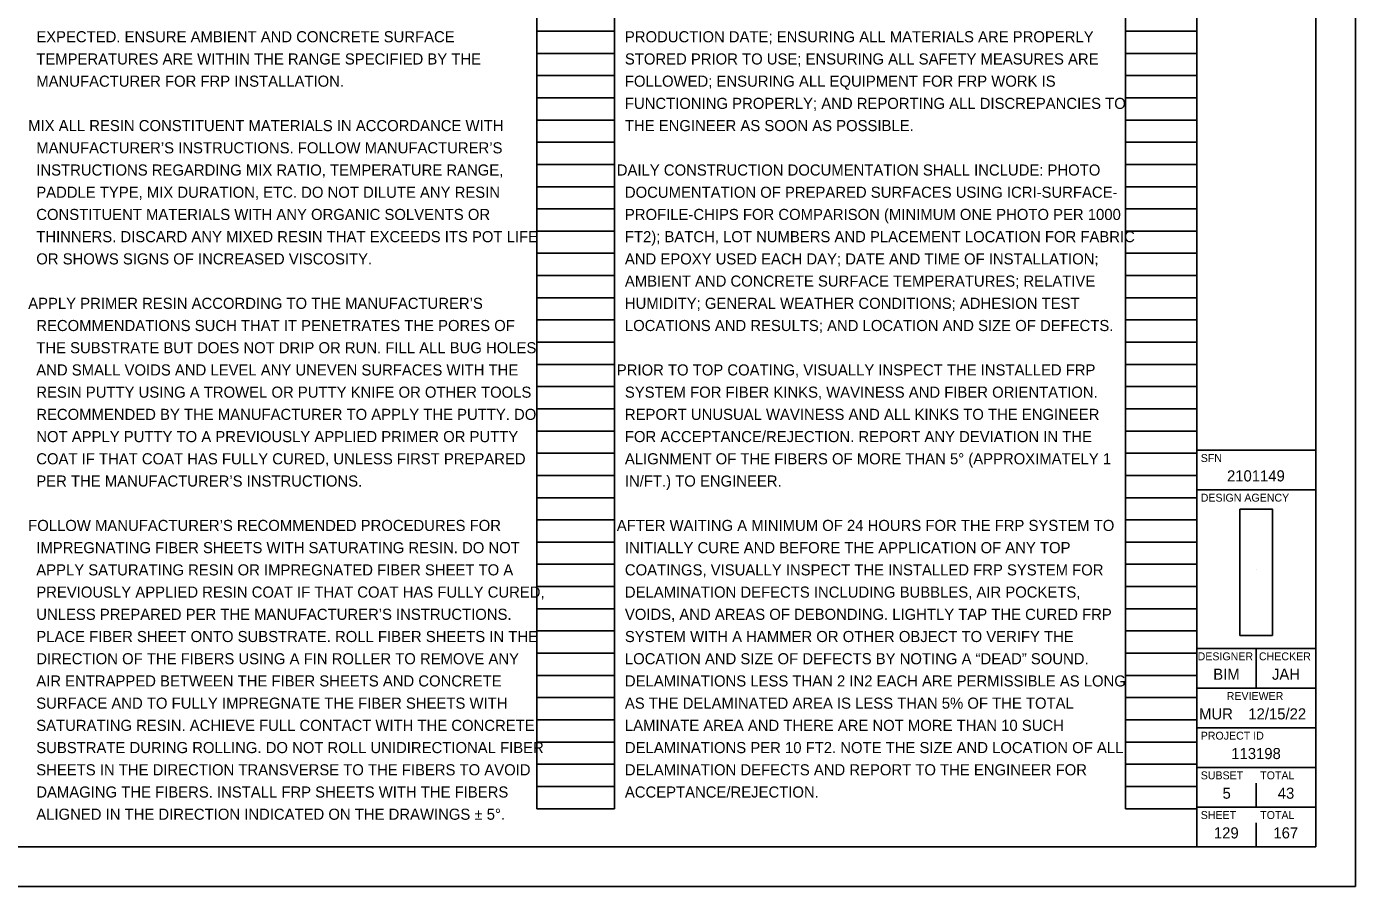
# Model space of a CAD drawing. Extents: x 0 to 90.2, y -3.7 to 22.
# Drawn here: x 17.25 to 34, y 0 to 10.84 of the extents above; entities that cross this region are included whole.
import ezdxf

# ---------------------------------------------------------------- set-up
doc = ezdxf.new("R2010")
doc.units = 0
for name, color, linetype in [('Default', 7, 'Continuous'), ('SH_Border', 7, 'Continuous'), ('SH_Cut_Line', 7, 'Continuous'), ('SH_Data', 7, 'Continuous'), ('SH_Text', 7, 'Continuous')]:
    doc.layers.add(name, color=color, linetype=linetype)

msp = doc.modelspace()

# ---------------------------------------------------------------- linework, layer by layer
at = {"layer": 'SH_Border'}
for p, q in [((32, 0.5), (32, 21.5)), ((32, 5.5), (33.5, 5.5)), ((32, 5), (33.5, 5)), ((32, 3), (33.5, 3)), ((32.75, 3), (32.75, 2.5)), ((32, 2.5), (33.5, 2.5)), ((32, 2), (33.5, 2)), ((32, 1.5), (33.5, 1.5)), ((32, 1), (33.5, 1))]:
    msp.add_line(p, q, dxfattribs=at)
msp.add_lwpolyline([(1.5, 21.5), (33.5, 21.5), (33.5, 0.5), (1.5, 0.5)], close=True, dxfattribs=at)
at = {"layer": 'SH_Cut_Line'}
msp.add_lwpolyline([(0, 0), (34, 0), (34, 22), (0, 22)], close=True, dxfattribs=at)
at = {"layer": 'SH_Data'}
for p, q in [((23.68, 0.98), (23.68, 21.14)), ((24.66, 0.98), (24.66, 21.14)), ((31.1, 0.98), (31.1, 21.14)), ((32, 0.98), (32, 21.14)), ((23.68, 10.78), (24.66, 10.78)), ((31.1, 10.78), (32, 10.78)), ((23.68, 10.5), (24.66, 10.5)), ((31.1, 10.5), (32, 10.5)), ((23.68, 10.22), (24.66, 10.22)), ((31.1, 10.22), (32, 10.22)), ((23.68, 9.94), (24.66, 9.94)), ((31.1, 9.94), (32, 9.94)), ((23.68, 9.66), (24.66, 9.66)), ((31.1, 9.66), (32, 9.66)), ((23.68, 9.38), (24.66, 9.38)), ((31.1, 9.38), (32, 9.38)), ((23.68, 9.1), (24.66, 9.1)), ((31.1, 9.1), (32, 9.1)), ((23.68, 8.82), (24.66, 8.82)), ((31.1, 8.82), (32, 8.82)), ((23.68, 8.54), (24.66, 8.54)), ((31.1, 8.54), (32, 8.54)), ((23.68, 8.26), (24.66, 8.26)), ((31.1, 8.26), (32, 8.26)), ((23.68, 7.98), (24.66, 7.98)), ((31.1, 7.98), (32, 7.98)), ((23.68, 7.7), (24.66, 7.7)), ((31.1, 7.7), (32, 7.7)), ((23.68, 7.42), (24.66, 7.42)), ((31.1, 7.42), (32, 7.42)), ((23.68, 7.14), (24.66, 7.14)), ((31.1, 7.14), (32, 7.14)), ((23.68, 6.86), (24.66, 6.86)), ((31.1, 6.86), (32, 6.86)), ((23.68, 6.58), (24.66, 6.58)), ((31.1, 6.58), (32, 6.58)), ((23.68, 6.3), (24.66, 6.3)), ((31.1, 6.3), (32, 6.3)), ((23.68, 6.02), (24.66, 6.02)), ((31.1, 6.02), (32, 6.02)), ((23.68, 5.74), (24.66, 5.74)), ((31.1, 5.74), (32, 5.74)), ((23.68, 5.46), (24.66, 5.46)), ((31.1, 5.46), (32, 5.46)), ((23.68, 5.18), (24.66, 5.18)), ((31.1, 5.18), (32, 5.18)), ((23.68, 4.9), (24.66, 4.9)), ((31.1, 4.9), (32, 4.9)), ((23.68, 4.62), (24.66, 4.62)), ((31.1, 4.62), (32, 4.62)), ((23.68, 4.34), (24.66, 4.34)), ((31.1, 4.34), (32, 4.34)), ((23.68, 4.06), (24.66, 4.06)), ((31.1, 4.06), (32, 4.06)), ((32.75, 4), (32.75, 4)), ((23.68, 3.78), (24.66, 3.78)), ((31.1, 3.78), (32, 3.78)), ((23.68, 3.5), (24.66, 3.5)), ((31.1, 3.5), (32, 3.5)), ((23.68, 3.22), (24.66, 3.22)), ((31.1, 3.22), (32, 3.22)), ((23.68, 2.94), (24.66, 2.94)), ((31.1, 2.94), (32, 2.94)), ((23.68, 2.66), (24.66, 2.66)), ((31.1, 2.66), (32, 2.66)), ((23.68, 2.38), (24.66, 2.38)), ((31.1, 2.38), (32, 2.38)), ((23.68, 2.1), (24.66, 2.1)), ((31.1, 2.1), (32, 2.1)), ((23.68, 1.82), (24.66, 1.82)), ((31.1, 1.82), (32, 1.82)), ((23.68, 1.54), (24.66, 1.54)), ((31.1, 1.54), (32, 1.54)), ((23.68, 1.26), (24.66, 1.26)), ((31.1, 1.26), (32, 1.26)), ((32.75, 1), (32.75, 1.3)), ((23.68, 0.98), (24.66, 0.98)), ((31.1, 0.98), (32, 0.98)), ((32.375, 0.675), (32.375, 0.675)), ((32.75, 0.5), (32.75, 0.8))]:
    msp.add_line(p, q, dxfattribs=at)
at = {"layer": 'SH_Text'}
msp.add_lwpolyline([(32.956, 3.164), (32.956, 4.754), (32.544, 4.754), (32.544, 3.164)], close=True, dxfattribs=at)

# ---------------------------------------------------------------- texts
at = {"layer": 'Default'}
for s, p in [('EXPECTED. ENSURE AMBIENT AND CONCRETE SURFACE ', (17.371, 10.64)), ('PRODUCTION DATE; ENSURING ALL MATERIALS ARE PROPERLY ', (24.791, 10.64)), ('TEMPERATURES ARE WITHIN THE RANGE SPECIFIED BY THE ', (17.371, 10.36)), ('STORED PRIOR TO USE; ENSURING ALL SAFETY MEASURES ARE ', (24.791, 10.36)), ('MANUFACTURER FOR FRP INSTALLATION.', (17.371, 10.08)), ('FOLLOWED; ENSURING ALL EQUIPMENT FOR FRP WORK IS ', (24.791, 10.08)), ('FUNCTIONING PROPERLY; AND REPORTING ALL DISCREPANCIES TO ', (24.791, 9.8)), ('MIX ALL RESIN CONSTITUENT MATERIALS IN ACCORDANCE WITH ', (17.269, 9.52)), ('THE ENGINEER AS SOON AS POSSIBLE.', (24.791, 9.52)), ('MANUFACTURER’S INSTRUCTIONS. FOLLOW MANUFACTURER’S ', (17.371, 9.24)), ('INSTRUCTIONS REGARDING MIX RATIO, TEMPERATURE RANGE, ', (17.371, 8.96)), ('DAILY CONSTRUCTION DOCUMENTATION SHALL INCLUDE: PHOTO ', (24.689, 8.96)), ('PADDLE TYPE, MIX DURATION, ETC. DO NOT DILUTE ANY RESIN ', (17.371, 8.68)), ('DOCUMENTATION OF PREPARED SURFACES USING ICRI-SURFACE-', (24.791, 8.68)), ('PROFILE-CHIPS FOR COMPARISON (MINIMUM ONE PHOTO PER 1000 ', (24.791, 8.4)), ('CONSTITUENT MATERIALS WITH ANY ORGANIC SOLVENTS OR ', (17.371, 8.4)), ('THINNERS. DISCARD ANY MIXED RESIN THAT EXCEEDS ITS POT LIFE ', (17.371, 8.12)), ('FT2); BATCH, LOT NUMBERS AND PLACEMENT LOCATION FOR FABRIC ', (24.791, 8.12)), ('OR SHOWS SIGNS OF INCREASED VISCOSITY.', (17.371, 7.84)), ('AND EPOXY USED EACH DAY; DATE AND TIME OF INSTALLATION; ', (24.791, 7.84)), ('AMBIENT AND CONCRETE SURFACE TEMPERATURES; RELATIVE ', (24.791, 7.56)), ('APPLY PRIMER RESIN ACCORDING TO THE MANUFACTURER’S ', (17.269, 7.28)), ('HUMIDITY; GENERAL WEATHER CONDITIONS; ADHESION TEST ', (24.791, 7.28)), ('RECOMMENDATIONS SUCH THAT IT PENETRATES THE PORES OF ', (17.371, 7)), ('LOCATIONS AND RESULTS; AND LOCATION AND SIZE OF DEFECTS.', (24.791, 7)), ('THE SUBSTRATE BUT DOES NOT DRIP OR RUN. FILL ALL BUG HOLES ', (17.371, 6.72)), ('AND SMALL VOIDS AND LEVEL ANY UNEVEN SURFACES WITH THE ', (17.371, 6.44)), ('PRIOR TO TOP COATING, VISUALLY INSPECT THE INSTALLED FRP ', (24.689, 6.44)), ('RESIN PUTTY USING A TROWEL OR PUTTY KNIFE OR OTHER TOOLS ', (17.371, 6.16)), ('SYSTEM FOR FIBER KINKS, WAVINESS AND FIBER ORIENTATION. ', (24.791, 6.16)), ('RECOMMENDED BY THE MANUFACTURER TO APPLY THE PUTTY. DO ', (17.371, 5.88)), ('REPORT UNUSUAL WAVINESS AND ALL KINKS TO THE ENGINEER ', (24.791, 5.88)), ('NOT APPLY PUTTY TO A PREVIOUSLY APPLIED PRIMER OR PUTTY ', (17.371, 5.6)), ('FOR ACCEPTANCE/REJECTION. REPORT ANY DEVIATION IN THE ', (24.791, 5.6)), ('COAT IF THAT COAT HAS FULLY CURED, UNLESS FIRST PREPARED ', (17.371, 5.32)), ('ALIGNMENT OF THE FIBERS OF MORE THAN 5° (APPROXIMATELY 1 ', (24.791, 5.32)), ('PER THE MANUFACTURER’S INSTRUCTIONS.', (17.371, 5.04)), ('IN/FT.) TO ENGINEER.', (24.791, 5.04)), ('FOLLOW MANUFACTURER’S RECOMMENDED PROCEDURES FOR ', (17.269, 4.48)), ('AFTER WAITING A MINIMUM OF 24 HOURS FOR THE FRP SYSTEM TO ', (24.689, 4.48)), ('IMPREGNATING FIBER SHEETS WITH SATURATING RESIN. DO NOT ', (17.371, 4.2)), ('INITIALLY CURE AND BEFORE THE APPLICATION OF ANY TOP ', (24.791, 4.2)), ('APPLY SATURATING RESIN OR IMPREGNATED FIBER SHEET TO A ', (17.371, 3.92)), ('COATINGS, VISUALLY INSPECT THE INSTALLED FRP SYSTEM FOR ', (24.791, 3.92)), ('PREVIOUSLY APPLIED RESIN COAT IF THAT COAT HAS FULLY CURED, ', (17.371, 3.64)), ('DELAMINATION DEFECTS INCLUDING BUBBLES, AIR POCKETS, ', (24.791, 3.64)), ('UNLESS PREPARED PER THE MANUFACTURER’S INSTRUCTIONS. ', (17.371, 3.36)), ('VOIDS, AND AREAS OF DEBONDING. LIGHTLY TAP THE CURED FRP ', (24.791, 3.36)), ('PLACE FIBER SHEET ONTO SUBSTRATE. ROLL FIBER SHEETS IN THE ', (17.371, 3.08)), ('SYSTEM WITH A HAMMER OR OTHER OBJECT TO VERIFY THE ', (24.791, 3.08)), ('DIRECTION OF THE FIBERS USING A FIN ROLLER TO REMOVE ANY ', (17.371, 2.8)), ('LOCATION AND SIZE OF DEFECTS BY NOTING A “DEAD” SOUND. ', (24.791, 2.8)), ('AIR ENTRAPPED BETWEEN THE FIBER SHEETS AND CONCRETE ', (17.371, 2.52)), ('DELAMINATIONS LESS THAN 2 IN2 EACH ARE PERMISSIBLE AS LONG ', (24.791, 2.52)), ('SURFACE AND TO FULLY IMPREGNATE THE FIBER SHEETS WITH ', (17.371, 2.24)), ('AS THE DELAMINATED AREA IS LESS THAN 5% OF THE TOTAL ', (24.791, 2.24)), ('SATURATING RESIN. ACHIEVE FULL CONTACT WITH THE CONCRETE ', (17.371, 1.96)), ('LAMINATE AREA AND THERE ARE NOT MORE THAN 10 SUCH ', (24.791, 1.96)), ('SUBSTRATE DURING ROLLING. DO NOT ROLL UNIDIRECTIONAL FIBER ', (17.371, 1.68)), ('DELAMINATIONS PER 10 FT2. NOTE THE SIZE AND LOCATION OF ALL ', (24.791, 1.68)), ('SHEETS IN THE DIRECTION TRANSVERSE TO THE FIBERS TO AVOID ', (17.371, 1.4)), ('DELAMINATION DEFECTS AND REPORT TO THE ENGINEER FOR ', (24.791, 1.4)), ('DAMAGING THE FIBERS. INSTALL FRP SHEETS WITH THE FIBERS ', (17.371, 1.12)), ('ACCEPTANCE/REJECTION.', (24.791, 1.12)), ('ALIGNED IN THE DIRECTION INDICATED ON THE DRAWINGS ± 5°.', (17.371, 0.84))]:
    msp.add_text(s, height=0.14, dxfattribs=at).set_placement(p)
at = {"layer": 'SH_Data'}
for s, height, p in [('SFN', 0.1, (32.05, 5.35)), ('2101149', 0.14, (32.381, 5.105)), ('DESIGN AGENCY', 0.1, (32.05, 4.85)), ('DESIGNER', 0.1, (32.011, 2.85)), ('CHECKER', 0.1, (32.784, 2.85)), ('BIM', 0.14, (32.208, 2.605)), ('JAH', 0.14, (32.948, 2.605)), ('REVIEWER', 0.1, (32.378, 2.35)), ('MUR', 0.14, (32.029, 2.105)), ('12/15/22', 0.14, (32.65, 2.105)), ('PROJECT ID', 0.1, (32.05, 1.85)), ('113198', 0.14, (32.435, 1.605)), ('SUBSET', 0.1, (32.05, 1.35)), ('TOTAL', 0.1, (32.8, 1.35)), ('5', 0.14, (32.325, 1.105)), ('43', 0.14, (33.021, 1.105)), ('SHEET', 0.1, (32.05, 0.85)), ('TOTAL', 0.1, (32.8, 0.85)), ('129', 0.14, (32.216, 0.605)), ('167', 0.14, (32.966, 0.605))]:
    msp.add_text(s, height=height, dxfattribs=at).set_placement(p)

doc.saveas('drawing.dxf')
